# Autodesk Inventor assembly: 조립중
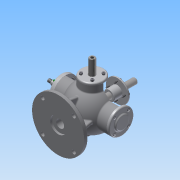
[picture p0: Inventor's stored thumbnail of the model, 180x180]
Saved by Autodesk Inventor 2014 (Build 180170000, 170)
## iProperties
Created: 2016-01
Part Number: 조립중
Document SubType Name: Assembly
Designer: Administrator
Author: Administrator
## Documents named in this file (12)
- C:\Users\Administrator\Desktop\360108V1014\조립중.iam
- C:\Users\Administrator\Desktop\360108V1014\본체.ipt
- C:\Users\Administrator\Desktop\360108V1014\앞커버.ipt
- C:\Users\Administrator\Desktop\360108V1014\뒤커버.ipt
- C:\Users\Administrator\Desktop\360108V1014\베어링- 6202.ipt
- C:\Users\Administrator\Desktop\360108V1014\축.ipt
- C:\Users\Administrator\Desktop\360108V1014\본체커버.ipt
- C:\Users\Administrator\Desktop\360108V1014\볼트 M4x0.7.ipt
- C:\Users\Administrator\Desktop\360108V1014\슬라이드.ipt
- C:\Users\Administrator\Desktop\360108V1014\키-4x4.ipt
- C:\Users\Administrator\Desktop\360108V1014\오일실.ipt
- C:\Users\Administrator\Desktop\360108V1014\슬라이드 커버.ipt
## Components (17 placed, 1 different names)
1. M4x0.7x12:5
2. M4x0.7x12:1
3. M4x0.7x12:2
4. M4x0.7x12:3
5. M4x0.7x12:4
6. M4x0.7x12:6
7. M4x0.7x12:7
8. M4x0.7x12:8
9. M4x0.7x12:9
10. M4x0.7x12:10
11. M4x0.7x12:11
12. M4x0.7x12:12
13. M4x0.7x12:13
14. M4x0.7x12:14
15. M4x0.7x12:15
16. M4x0.7x12:16
17. M4x0.7x12:17
